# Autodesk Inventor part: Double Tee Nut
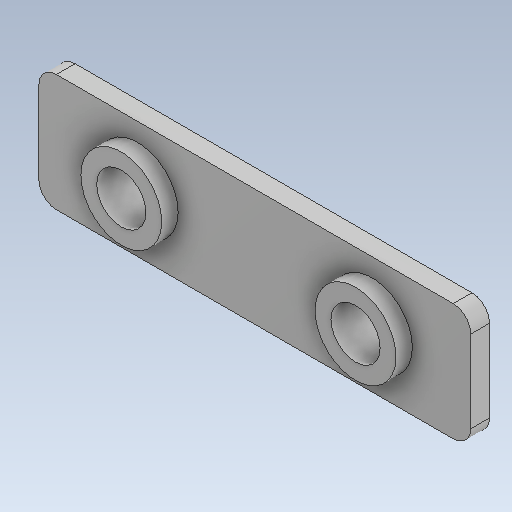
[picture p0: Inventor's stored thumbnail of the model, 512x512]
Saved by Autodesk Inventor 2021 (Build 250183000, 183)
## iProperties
Created: 2026-10
Part Number: Double Tee Nut
Material: Steel
Document SubType Name: Modeling
Designer: hp
Density: 7.85 g/cm^3
Appearance: Default
Author: hp
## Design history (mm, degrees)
feature "Body1"
body "Solid1"
